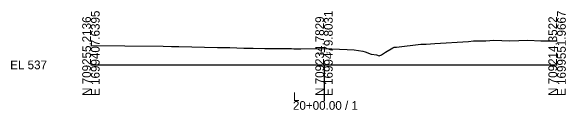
# Model space of a CAD drawing. Extents: x -63 to 1153, y -24 to 9522.
# Drawn here: x 974.3 to 1152.8, y 3485.5 to 3517.3 of the extents above; entities that cross this region are included whole.
import ezdxf

# ---------------------------------------------------------------- set-up
doc = ezdxf.new("R2010")
doc.units = 0
for name, color, linetype in [('Default', 7, 'Continuous'), ('Exist Cross Section Cell', 7, 'Continuous'), ('Exist XS Center Line Elevation Label', 7, 'Continuous'), ('Exist XS Ground Line', 7, 'Continuous')]:
    doc.layers.add(name, color=color, linetype=linetype)

msp = doc.modelspace()

# ---------------------------------------------------------------- linework, layer by layer
at = {"layer": 'Exist Cross Section Cell'}
for p, q in [((1000, 3500), (1075, 3500)), ((1075, 3500), (1150, 3500)), ((1075, 3500), (1075, 3488.34))]:
    msp.add_line(p, q, dxfattribs=at)
at = {"layer": 'Exist XS Ground Line'}
msp.add_lwpolyline([(1000, 3506.23), (1010.87, 3506.15), (1023.27, 3506.03), (1025.92, 3505.95), (1026.86, 3505.94), (1028.27, 3505.91), (1040.72, 3505.65), (1044.68, 3505.55), (1049.21, 3505.41), (1052.2, 3505.34), (1056, 3505.3), (1057.92, 3505.27), (1059.25, 3505.23), (1061, 3505.23), (1062.01, 3505.31), (1064.55, 3505.25), (1065.27, 3505.14), (1065.32, 3505.17), (1067.56, 3505.2), (1075, 3505.27), (1075.08, 3505.27), (1082.46, 3504.97), (1084.68, 3504.86), (1084.72, 3504.83), (1087.47, 3504.45), (1088.27, 3504.24), (1090.22, 3503.45), (1090.24, 3503.44), (1090.27, 3503.43), (1091.84, 3503.22), (1092.7, 3502.89), (1093.54, 3503.22), (1094.74, 3504.11), (1097.1, 3505.45), (1097.53, 3505.7), (1098.34, 3505.75), (1106.2, 3506.63), (1107.89, 3506.66), (1110.61, 3506.91), (1121.52, 3507.58), (1123.09, 3507.79), (1126.97, 3507.72), (1126.99, 3507.72), (1127.04, 3507.72), (1127.12, 3507.73), (1129.68, 3508.01), (1134.78, 3507.77), (1140.59, 3507.91), (1144.72, 3507.8), (1149.54, 3507.72), (1150, 3507.71)], dxfattribs=at)

# ---------------------------------------------------------------- texts
at = {"layer": 'Default'}
msp.add_text('-', height=0.0001, dxfattribs=at).set_placement((1000, 3500))
at = {"layer": 'Exist Cross Section Cell'}
for s, p in [('E 1699407.6395', (1002.8, 3490)), ('E 1699479.8031', (1077.8, 3490)), ('E 1699551.9667', (1152.8, 3490)), ('N 709255.2136', (1000, 3490)), ('N 709234.7829', (1075, 3490)), ('N 709214.3522', (1150, 3490))]:
    msp.add_text(s, height=2.8, rotation=90, dxfattribs=at).set_placement(p)
for s, p in [('EL 537', (974, 3498.6)), ('L', (1065, 3488.34)), ('20+00.00 / 1', (1065, 3485.54))]:
    msp.add_text(s, height=2.8, dxfattribs=at).set_placement(p)
at = {"layer": 'Exist XS Center Line Elevation Label'}
msp.add_text('542.27', height=1, dxfattribs=at).set_placement((1072.85, 3503.2))

doc.saveas('drawing.dxf')
